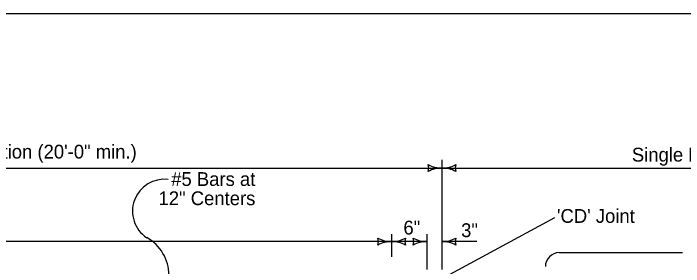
# Model space of a CAD drawing. Extents: x 8925 to 81668, y 4369 to 11918.
# Drawn here: x 11330 to 12301, y 9577 to 9944 of the extents above; entities that cross this region are included whole.
import ezdxf

# ---------------------------------------------------------------- set-up
doc = ezdxf.new("R2010")
doc.units = 0
for name, color, linetype in [('dsnShtPlotShapeBatchPrint', 7, 'Continuous'), ('Level 3', 7, 'Continuous'), ('SheetBorder', 7, 'Continuous')]:
    doc.layers.add(name, color=color, linetype=linetype)

msp = doc.modelspace()

# ---------------------------------------------------------------- linework, layer by layer
at = {"layer": 'dsnShtPlotShapeBatchPrint'}
for p, q in [((11950.96, 9572.8), (11950.96, 9732.01)), ((10578.72, 9719.96), (11950.96, 9719.96)), ((11950.96, 9719.96), (12919.59, 9719.96)), ((11950.96, 9559.76), (12114.15, 9648.09)), ((11878.03, 9591.42), (11878.03, 9623.99)), ((11929.18, 9572.8), (11929.18, 9623.99)), ((11878.03, 9613.4), (11252.06, 9613.4)), ((11929.18, 9613.4), (11878.03, 9613.4)), ((12001.36, 9613.4), (11950.96, 9613.4)), ((12120.84, 9597.36), (12299.31, 9597.36))]:
    msp.add_line(p, q, dxfattribs=at)
for centre, radius, start, end in [((11548.5, 9657.6), 46.06, 82.93387, 236.76687), ((11492.57, 9564.1), 62.96, 300.6735, 60.83314), ((12120.84, 9577.16), 20.21, 90, 180)]:
    msp.add_arc(centre, radius, start, end, dxfattribs=at)
at = {"layer": 'Level 3'}
for centre, radius, start, end in [((11915.33, 9719.96), 16.42, 342.26665, 17.73335), ((11950.96, 9762.46), 42.5, 241.92751, 270), ((11950.96, 9677.46), 42.5, 90, 118.07249), ((11950.96, 9762.46), 42.5, 270, 298.07249), ((11950.96, 9677.46), 42.5, 61.92751, 90), ((11986.6, 9719.96), 16.42, 162.26665, 197.73335), ((11842.39, 9613.4), 16.42, 342.26665, 17.73335), ((11878.03, 9655.9), 42.5, 241.92751, 270), ((11878.03, 9570.9), 42.5, 90, 118.07249), ((11878.03, 9655.9), 42.5, 270, 298.07249), ((11878.03, 9570.9), 42.5, 61.92751, 90), ((11913.66, 9613.4), 16.42, 162.26665, 197.73335), ((11893.54, 9613.4), 16.42, 342.26665, 17.73335), ((11929.18, 9655.9), 42.5, 241.92751, 270), ((11929.18, 9570.9), 42.5, 90, 118.07249), ((11950.96, 9655.9), 42.5, 270, 298.07249), ((11950.96, 9570.9), 42.5, 61.92751, 90), ((11986.6, 9613.4), 16.42, 162.26665, 197.73335)]:
    msp.add_arc(centre, radius, start, end, dxfattribs=at)
at = {"layer": 'SheetBorder'}
msp.add_lwpolyline([(10132.52, 9944.02), (13267.53, 9944.02), (13267.53, 7924.02), (10132.52, 7924.02)], close=True, dxfattribs=at)

# ---------------------------------------------------------------- texts
at = {"layer": 'dsnShtPlotShapeBatchPrint'}
for s, p in [('Double Reinforced Section (20\'-0" min.)', (11039.18, 9733.7)), ('Single Reinforced Section (20\'-0")', (12225.98, 9729.35)), ('#5 Bars at', (11558.59, 9694)), ('12" Centers', (11540.2, 9666.17)), ("'CD' Joint", (12117.48, 9640.54)), ('6"', (11895, 9623.67)), ('3"', (11978.58, 9619.86))]:
    msp.add_text(s, height=20, dxfattribs=at).set_placement(p)

doc.saveas('drawing.dxf')
